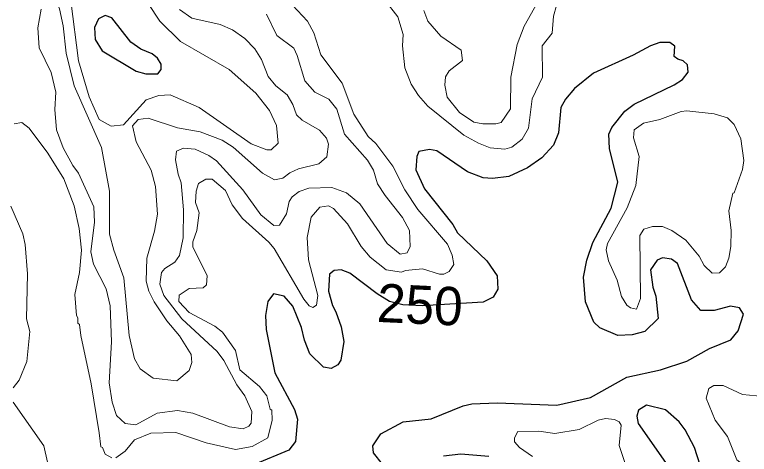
# Model space of a CAD drawing. Extents: x 763.2 to 816.8, y 7896.5 to 7952.7.
# Drawn here: x 788.764 to 791.829, y 7912.79 to 7914.625 of the extents above; entities that cross this region are included whole.
import ezdxf
from ezdxf.enums import TextEntityAlignment as Align

# ---------------------------------------------------------------- set-up
doc = ezdxf.new("R2010")
doc.units = 0
doc.header["$LTSCALE"] = 0.064
doc.layers.add('1', color=7, linetype='Continuous', lineweight=25)
doc.layers.add('2', color=7, linetype='Continuous', lineweight=13)
doc.layers.add('61', color=7, linetype='Continuous')

msp = doc.modelspace()

# ---------------------------------------------------------------- linework, layer by layer
at = {"layer": '1'}
msp.add_lwpolyline([(789.2897, 7914.4811), (789.2493, 7914.5094), (789.1691, 7914.612), (789.1412, 7914.6218), (789.1137, 7914.6077), (789.0972, 7914.5711), (789.0999, 7914.5207), (789.1289, 7914.4739), (789.2705, 7914.3891), (789.3106, 7914.3773), (789.3614, 7914.3775), (789.3756, 7914.3964), (789.3747, 7914.4176), (789.3597, 7914.4428), (789.338, 7914.4616)], close=True, dxfattribs=at)
for points in [[(790.299, 7912.7494), (790.2607, 7912.7963), (790.2575, 7912.8256), (790.291, 7912.8755), (790.3848, 7912.9257), (790.5016, 7912.938), (790.6353, 7912.9933), (790.6713, 7913.0016), (790.7773, 7913.0049), (791.0263, 7912.9952), (791.1658, 7913.0272), (791.3179, 7913.1119), (791.4586, 7913.1435), (791.5683, 7913.1788), (791.6624, 7913.2316), (791.7518, 7913.2682), (791.7822, 7913.3052), (791.8049, 7913.3756), (791.7881, 7913.4015), (791.75, 7913.4092), (791.6821, 7913.3899), (791.6259, 7913.391), (791.5881, 7913.4346), (791.5293, 7913.5859), (791.5044, 7913.6047), (791.4668, 7913.6095), (791.4439, 7913.6), (791.4164, 7913.5595), (791.4269, 7913.4882), (791.4389, 7913.4496), (791.4487, 7913.3566), (791.3934, 7913.3029), (791.3398, 7913.289), (791.2805, 7913.2863), (791.2046, 7913.3185), (791.1797, 7913.3418), (791.145, 7913.4266), (791.1366, 7913.5298), (791.1511, 7913.6008), (791.1759, 7913.6738), (791.2526, 7913.8177), (791.2808, 7913.9262), (791.246, 7914.0664), (791.2433, 7914.1258), (791.2551, 7914.1544), (791.3099, 7914.222), (791.3478, 7914.2518), (791.5154, 7914.3325), (791.5494, 7914.3549), (791.5735, 7914.3845), (791.5709, 7914.4159), (791.5525, 7914.4325), (791.5309, 7914.4397), (791.5146, 7914.4505), (791.518, 7914.4932), (791.4971, 7914.5085), (791.4554, 7914.5086), (791.4168, 7914.4952), (791.3444, 7914.4557), (791.1782, 7914.3807)], [(791.1782, 7914.3807), (791.0992, 7914.3169), (791.0618, 7914.2717), (791.0428, 7914.2381), (791.0328, 7914.1315), (791.0125, 7914.0809)], [(791.0125, 7914.0809), (790.9628, 7914.0268), (790.9028, 7913.9853), (790.8261, 7913.9496), (790.7568, 7913.9418), (790.719, 7913.9438), (790.6526, 7913.9685), (790.5249, 7914.0566), (790.4942, 7914.0615), (790.4506, 7914.054), (790.4412, 7914.0329), (790.4381, 7913.977), (790.4742, 7913.8979), (790.5923, 7913.7494), (790.6119, 7913.7151), (790.7336, 7913.5982), (790.7763, 7913.5354), (790.7795, 7913.4793), (790.7604, 7913.4462), (790.7179, 7913.4255), (790.464, 7913.4101), (790.3835, 7913.4138), (790.3281, 7913.4278), (790.276, 7913.4597), (790.1627, 7913.5459), (790.1257, 7913.5602), (790.0963, 7913.5568), (790.0779, 7913.5427), (790.0733, 7913.4709), (790.0897, 7913.411), (790.1045, 7913.3855), (790.1254, 7913.3228), (790.1371, 7913.2615), (790.1253, 7913.1832), (790.1123, 7913.1631), (790.0847, 7913.1482), (790.0529, 7913.1534), (789.9953, 7913.2092), (789.9728, 7913.2669), (789.961, 7913.3195), (789.9247, 7913.4082), (789.8877, 7913.4498), (789.8443, 7913.4595), (789.8202, 7913.4273), (789.8102, 7913.3697), (789.8131, 7913.3118), (789.8487, 7913.1301), (789.9316, 7912.977), (789.9433, 7912.9369), (789.9349, 7912.8443), (789.9075, 7912.8083), (789.7674, 7912.7487)], [(791.6473, 7912.6716), (791.6001, 7912.8185), (791.5609, 7912.893), (791.5357, 7912.926), (791.4787, 7912.9765), (791.3993, 7912.9949), (791.3665, 7912.9746), (791.36, 7912.9502), (791.3645, 7912.9193), (791.5177, 7912.7009)], [(790.742, 7912.7813), (790.6254, 7912.7913), (790.5523, 7912.7828)]]:
    msp.add_lwpolyline(points, dxfattribs=at)
at = {"layer": '2'}
for points in [[(788.759, 7915.0467), (788.7945, 7914.9984), (788.8393, 7914.8795), (788.8982, 7914.7809), (788.9515, 7914.6491), (788.9668, 7914.5784), (788.9783, 7914.4642), (789.012, 7914.3283), (789.1269, 7914.0701)], [(789.3208, 7914.6717), (789.3697, 7914.5975), (789.4558, 7914.513), (789.6585, 7914.3961), (789.7707, 7914.2967), (789.8265, 7914.2243), (789.8561, 7914.1618), (789.8627, 7914.0882), (789.8337, 7914.0604), (789.8161, 7914.0603), (789.7511, 7914.0864), (789.534, 7914.2375), (789.4131, 7914.2899), (789.3653, 7914.2873), (789.3128, 7914.2689), (789.2177, 7914.1652), (789.1672, 7914.159), (789.1172, 7914.188), (789.0753, 7914.2826), (789.0307, 7914.4315), (788.9983, 7914.6823)], [(790.3079, 7914.6868), (790.3619, 7914.6161), (790.3852, 7914.5416), (790.3821, 7914.4948), (790.392, 7914.4036), (790.4181, 7914.3352), (790.4483, 7914.288), (790.4883, 7914.243), (790.6373, 7914.1215), (790.6987, 7914.0883), (790.7483, 7914.0697), (790.8086, 7914.0634), (790.8383, 7914.0715), (790.8805, 7914.105), (790.9079, 7914.1514), (790.9232, 7914.2735), (790.9654, 7914.3642), (790.964, 7914.4948), (791.0063, 7914.5482), (791.0119, 7914.6187), (791.0245, 7914.6625)], [(790.9449, 7914.6751), (790.8892, 7914.5765), (790.8597, 7914.4998), (790.8341, 7914.3641), (790.8322, 7914.2316), (790.7932, 7914.1755), (790.7718, 7914.1686), (790.7167, 7914.1687), (790.6802, 7914.1767), (790.6204, 7914.2163), (790.5679, 7914.281), (790.558, 7914.3306), (790.5616, 7914.3647), (790.5762, 7914.3902), (790.6319, 7914.4341), (790.6264, 7914.476), (790.5418, 7914.5357), (790.4873, 7914.5974), (790.4713, 7914.6427)], [(789.8146, 7914.6275), (789.8583, 7914.5379), (789.9285, 7914.485), (789.9432, 7914.4539), (789.9741, 7914.3492), (790.0165, 7914.3007), (790.0742, 7914.2722), (790.1075, 7914.2308), (790.1397, 7914.1262), (790.2366, 7914.0177), (790.2603, 7913.9762), (790.2781, 7913.9183), (790.309, 7913.87), (790.3819, 7913.779), (790.4114, 7913.724), (790.4146, 7913.6571), (790.4014, 7913.6314), (790.3719, 7913.625), (790.3186, 7913.6702), (790.2041, 7913.8354), (790.1487, 7913.8809), (790.0872, 7913.9041), (789.9916, 7913.9006), (789.9503, 7913.8866), (789.922, 7913.8643), (789.9093, 7913.8455), (789.8984, 7913.7941), (789.8691, 7913.7464), (789.8453, 7913.7447), (789.7916, 7913.7894), (789.7161, 7913.8945), (789.6058, 7914.0144), (789.5744, 7914.0373), (789.5176, 7914.0633), (789.4683, 7914.0681), (789.4393, 7914.055), (789.4355, 7914.0196), (789.4456, 7913.9592), (789.4584, 7913.923), (789.4682, 7913.81), (789.4666, 7913.6942), (789.4515, 7913.6205), (789.4315, 7913.5914), (789.3901, 7913.5656), (789.3762, 7913.5496), (789.3699, 7913.5003), (789.3869, 7913.4524), (789.4607, 7913.3563), (789.6084, 7913.2196), (789.6362, 7913.1818), (789.6913, 7913.0804), (789.7237, 7913.0349), (789.7535, 7912.9692), (789.7511, 7912.9208), (789.7404, 7912.9079), (789.7171, 7912.8964), (789.66, 7912.9054), (789.5072, 7912.9623), (789.4434, 7912.9736), (789.3586, 7912.9617), (789.2696, 7912.913), (789.225, 7912.9188), (789.1891, 7912.953), (789.1707, 7913.0073), (789.1578, 7913.0882), (789.1676, 7913.2599), (789.1626, 7913.4102), (789.146, 7913.4805), (789.0923, 7913.5836), (789.0813, 7913.6352), (789.0969, 7913.7593), (789.0941, 7913.8229), (789.0309, 7913.9629), (789.0068, 7913.9948), (788.9665, 7914.0693), (788.938, 7914.1437), (788.931, 7914.2286), (788.9358, 7914.301), (788.9163, 7914.3832), (788.8663, 7914.4868), (788.8602, 7914.5701), (788.8748, 7914.6474)], [(789.1867, 7912.7754), (789.2249, 7912.8029), (789.264, 7912.8514), (789.3327, 7912.8786), (789.437, 7912.8814), (789.5633, 7912.8385), (789.6847, 7912.8111), (789.755, 7912.8229), (789.8199, 7912.8592), (789.838, 7912.9325), (789.8362, 7912.9745), (789.8301, 7912.9794), (789.8156, 7913.0343), (789.7849, 7913.0729), (789.703, 7913.1434), (789.6848, 7913.224), (789.6304, 7913.2996), (789.5992, 7913.3257), (789.492, 7913.3826), (789.4488, 7913.4281), (789.4501, 7913.4539), (789.4916, 7913.4829), (789.5499, 7913.4851), (789.564, 7913.4972), (789.5666, 7913.5344), (789.5078, 7913.6567), (789.5079, 7913.6771), (789.5243, 7913.7238), (789.5336, 7913.7983), (789.5178, 7913.8408), (789.5212, 7913.8882), (789.5311, 7913.9201), (789.5612, 7913.9383), (789.5875, 7913.9383), (789.6436, 7913.8909), (789.671, 7913.8311), (789.7147, 7913.7747), (789.8243, 7913.6759), (789.8463, 7913.6491), (789.9709, 7913.4379), (789.9931, 7913.4103), (790.0085, 7913.4035), (790.0234, 7913.4132), (790.0287, 7913.453), (789.9893, 7913.6022), (789.9844, 7913.695), (790.0011, 7913.7798), (790.0376, 7913.8217), (790.0736, 7913.8266), (790.0937, 7913.8159), (790.1519, 7913.7527), (790.2096, 7913.6575), (790.2467, 7913.6136), (790.3137, 7913.5603), (790.378, 7913.5506), (790.3939, 7913.5571), (790.4651, 7913.5637), (790.536, 7913.5426), (790.5548, 7913.5424), (790.5765, 7913.5527), (790.5955, 7913.5824), (790.5888, 7913.6219), (790.5693, 7913.6672), (790.4457, 7913.8125), (790.3911, 7913.8937), (790.3422, 7913.9932), (790.2709, 7914.0867), (790.2386, 7914.1168), (790.1784, 7914.2097), (790.1303, 7914.3385), (790.0417, 7914.457), (790.0115, 7914.549), (789.9855, 7914.598), (789.9232, 7914.6637)], [(789.2415, 7913.2867), (789.2641, 7913.1888), (789.2881, 7913.1475), (789.3411, 7913.1085), (789.4406, 7913.097), (789.4915, 7913.1404), (789.5024, 7913.1739), (789.501, 7913.2071), (789.4523, 7913.2854), (789.3982, 7913.3476), (789.3459, 7913.4261), (789.3236, 7913.4707), (789.313, 7913.5122), (789.3155, 7913.6081), (789.348, 7913.7216), (789.3598, 7913.7928), (789.3515, 7913.9079), (789.3337, 7913.9755), (789.2712, 7914.0946), (789.2552, 7914.1606), (789.279, 7914.187), (789.3214, 7914.1931), (789.4429, 7914.1527), (789.5373, 7914.1356), (789.6294, 7914.101), (789.6754, 7914.0715), (789.7974, 7913.9641), (789.8483, 7913.9352), (789.8822, 7913.9424), (789.9115, 7913.9643), (789.9476, 7913.9809), (790.0323, 7914.0029), (790.0669, 7914.0318), (790.0731, 7914.084), (790.0654, 7914.1091), (790.0358, 7914.1431), (789.9639, 7914.185), (789.9397, 7914.2065), (789.9249, 7914.2496), (789.9014, 7914.2904), (789.8531, 7914.3283), (789.821, 7914.3665), (789.7943, 7914.438), (789.7657, 7914.4824), (789.7247, 7914.5251), (789.6721, 7914.5612), (789.6211, 7914.5837), (789.5026, 7914.61), (789.4516, 7914.646)], [(788.7621, 7914.1697), (788.7938, 7914.1745), (788.8239, 7914.1518), (788.9029, 7914.0468), (788.9687, 7913.9401), (789.0126, 7913.8265), (789.0328, 7913.733), (789.0425, 7913.6424), (789.0342, 7913.5483), (789.0149, 7913.4576), (789.0214, 7913.3696)], [(789.1269, 7914.0701), (789.1592, 7913.8882), (789.1597, 7913.7086), (789.177, 7913.6424), (789.2199, 7913.5266), (789.2415, 7913.2867)], [(788.7577, 7913.0684), (788.7832, 7913.0995), (788.8141, 7913.1776), (788.8275, 7913.3026), (788.8127, 7913.3557), (788.8176, 7913.5434), (788.8073, 7913.6655), (788.7977, 7913.71), (788.7485, 7913.8257)], [(789.0214, 7913.3696), (789.0278, 7913.3592), (789.0281, 7913.3376), (789.0344, 7913.3325), (789.0395, 7913.2861), (789.0838, 7913.0848)], [(789.0838, 7913.0848), (789.1162, 7912.8799), (789.1229, 7912.8222), (789.1299, 7912.8185), (789.1418, 7912.7915), (789.1688, 7912.7761)], [(788.901, 7912.7583), (788.8861, 7912.8264), (788.7579, 7913.0081)], [(791.3092, 7912.7569), (791.286, 7912.8266), (791.2939, 7912.9121), (791.2857, 7912.9257), (791.2661, 7912.9357), (791.2284, 7912.9392), (791.1986, 7912.933), (791.1186, 7912.8935), (791.0172, 7912.8769), (790.9507, 7912.8866), (790.8626, 7912.8853), (790.8491, 7912.8587), (790.8494, 7912.842), (790.8698, 7912.8182), (790.9244, 7912.7814)]]:
    msp.add_lwpolyline(points, dxfattribs=at)
for points in [[(791.4673, 7913.741), (791.5062, 7913.7247), (791.5641, 7913.6832), (791.6191, 7913.6169), (791.6399, 7913.5781), (791.6732, 7913.5463), (791.7039, 7913.5477), (791.7293, 7913.5733), (791.7428, 7913.6082), (791.751, 7913.6574), (791.7526, 7913.7245), (791.743, 7913.8057), (791.7594, 7913.8797), (791.7658, 7913.882), (791.8001, 7913.979), (791.8054, 7914.0159), (791.794, 7914.107), (791.7657, 7914.1668), (791.7376, 7914.1946), (791.6823, 7914.2115), (791.568, 7914.2241), (791.544, 7914.2209), (791.455, 7914.1869), (791.388, 7914.1718), (791.3488, 7914.1444), (791.3455, 7914.1114), (791.3695, 7914.0332), (791.3559, 7913.9115), (791.3193, 7913.8193), (791.2367, 7913.6705), (791.2322, 7913.644), (791.2419, 7913.5976), (791.2774, 7913.5166), (791.2953, 7913.4483), (791.3173, 7913.4127), (791.3331, 7913.4017), (791.358, 7913.3965), (791.3745, 7913.4406), (791.3714, 7913.7027), (791.3892, 7913.7297), (791.4254, 7913.7413)], [(792.0479, 7912.888), (792.0366, 7912.8936), (791.9952, 7912.9528), (791.9214, 7913.019), (791.8882, 7913.031), (791.801, 7913.0405), (791.7198, 7913.0771), (791.6805, 7913.0772), (791.6597, 7913.065), (791.6491, 7913.0253), (791.6862, 7912.9331), (791.7378, 7912.8652), (791.7767, 7912.768), (791.8777, 7912.6881), (791.9144, 7912.6792), (791.9638, 7912.6532), (792.0036, 7912.65), (792.0418, 7912.6779), (792.0916, 7912.7385), (792.0959, 7912.7714), (792.0761, 7912.8392)]]:
    msp.add_lwpolyline(points, close=True, dxfattribs=at)

# ---------------------------------------------------------------- texts
at = {"layer": '61'}
msp.add_text('250', height=0.16, rotation=357.308, dxfattribs=at).set_placement((790.4508, 7913.3347), align=Align.CENTER)

doc.saveas('drawing.dxf')
